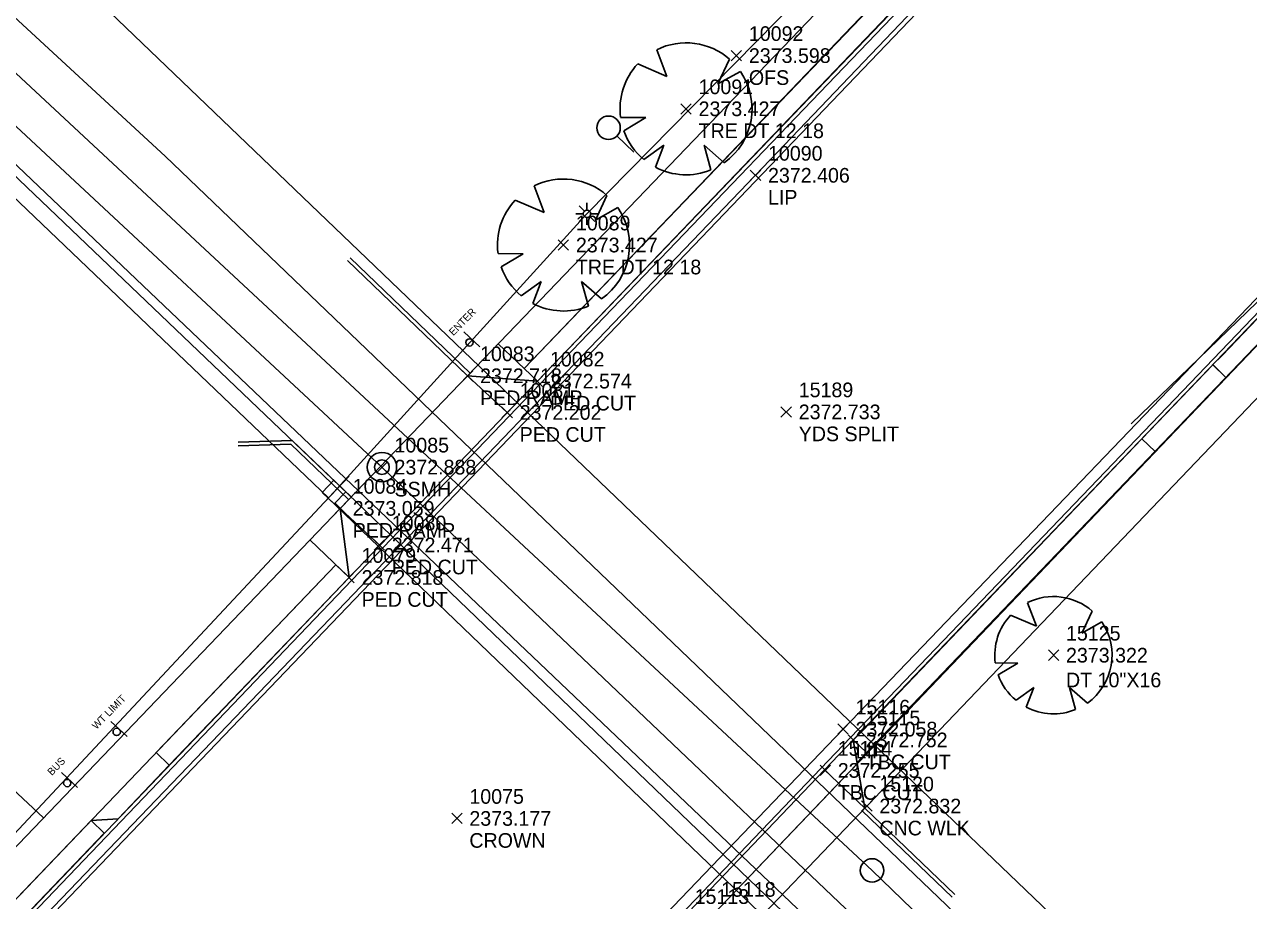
# Model space of a CAD drawing. Extents: x 2377639 to 2379738, y 729875 to 732734.
# Drawn here: x 2378181.6 to 2378348.5, y 730426.6 to 730546.1 of the extents above; entities that cross this region are included whole.
import ezdxf

# ---------------------------------------------------------------- set-up
doc = ezdxf.new("R2010")
doc.units = 0
for name, color, linetype in [('Default', 7, 'Continuous'), ('DES_ROADWAY_Sidewalk', 7, 'Continuous'), ('TOPO_CURBGTR_Back-of-Curb', 7, 'Continuous'), ('TOPO_CURBGTR_Face-of-Curb', 7, 'Continuous'), ('TOPO_CURBGTR_Lip-of-Gutter', 7, 'Continuous'), ('TOPO_DATA_Elevations', 7, 'Continuous'), ('TOPO_DATA_Notes', 7, 'Continuous'), ('TOPO_ELEC_Cable_Overhead-Exist', 7, 'Continuous'), ('TOPO_ELEC_Power-Pole', 7, 'Continuous'), ('TOPO_GAS_Line', 7, 'Continuous'), ('TOPO_LIGHTING_Luminaire-Pole', 7, 'Continuous'), ('TOPO_LNDSCP_Misc', 7, 'Continuous'), ('TOPO_LNDSCP_Tree', 7, 'Continuous'), ('TOPO_MISC_Flat-Asphalt', 7, 'Continuous'), ('TOPO_SAN_Plastic-Pipe', 7, 'Continuous'), ('TOPO_SAN_Sewer-Manhole', 7, 'Continuous'), ('TOPO_SIGNS_Post-Single', 7, 'Continuous'), ('TOPO_STORM_Line-Other', 7, 'Continuous'), ('TOPO_SW_Back', 7, 'Continuous'), ('TOPO_SW_Edge', 7, 'Continuous'), ('TOPO_TELE_Overhead-Line', 7, 'Continuous'), ('TOPO_TV_Cable-Overhead', 7, 'Continuous'), ('TOPO_WTRUTIL_Irrig-Sprinkler', 7, 'Continuous'), ('TOPO_WTRUTIL_Line', 7, 'Continuous'), ('TOPO_WTRUTIL_Spigot', 7, 'Continuous'), ('TOPO_WTRUTIL_Valve', 7, 'Continuous')]:
    doc.layers.add(name, color=color, linetype=linetype)

# ---------------------------------------------------------------- blocks, each defined once
blk = doc.blocks.new('MH_18')
at = {"layer": 'Default'}
for radius in [0.0254, 0.0127]:
    blk.add_circle((0, 0), radius, dxfattribs=at)
blk = doc.blocks.new('DT_1')
at = {"layer": 'Default'}
for p, q in [((-0.037, 0.0625), (-0.0565, 0.1137)), ((0.0838, 0.0954), (0.0615, 0.0479)), ((-0.093, 0.0865), (-0.037, 0.0625)), ((0.0615, 0.0479), (0.1046, 0.072)), ((-0.0773, -0.017), (-0.1259, -0.0164)), ((-0.1198, -0.0422), (-0.0773, -0.017)), ((-0.0426, -0.0702), (-0.0811, -0.0977)), ((-0.059, -0.1125), (-0.0426, -0.0702)), ((0.0734, -0.1037), (0.0346, -0.0702)), ((0.0346, -0.0702), (0.048, -0.1176))]:
    blk.add_line(p, q, dxfattribs=at)
for start, end in [(48.7013, 116.3979), (137.0682, 187.4038), (305.2865, 34.5379), (199.3985, 230.3084), (242.3287, 292.2114)]:
    blk.add_arc((0, 0), 0.127, start, end, dxfattribs=at)
blk = doc.blocks.new('SIGN_6')
at = {"layer": 'Default'}
blk.add_line((0.0064, 0.0197), (0.0064, -0.0185), dxfattribs=at)
blk.add_circle((0, 0), 0.00635, dxfattribs=at)
blk = doc.blocks.new('UP_1')
at = {"layer": 'Default'}
for p, q in [((0, 0.0381), (0, -0.0381)), ((-0.0145, 0.0145), (0.0145, 0.0145)), ((-0.0145, -0.0145), (-0.0145, 0.0145)), ((0.0145, 0.0145), (0.0145, -0.0145)), ((0.0145, -0.0145), (-0.0145, -0.0145))]:
    blk.add_line(p, q, dxfattribs=at)
blk = doc.blocks.new('LITE_2')
at = {"layer": 'Default'}
for p, q in [((-0.0064, 0), (-0.0191, 0)), ((-0.0045, 0.0045), (-0.0135, 0.0135)), ((0, 0.0191), (0, 0.0064)), ((0.0045, 0.0045), (0.0135, 0.0135)), ((0.0191, 0), (0.0064, 0)), ((-0.0135, -0.0135), (-0.0045, -0.0045)), ((0, -0.0064), (0, -0.0191)), ((0.0135, -0.0135), (0.0045, -0.0045))]:
    blk.add_line(p, q, dxfattribs=at)
blk.add_circle((0, 0), 0.00635, dxfattribs=at)

msp = doc.modelspace()

# ---------------------------------------------------------------- linework, layer by layer
at = {"layer": 'DES_ROADWAY_Sidewalk'}
for p, q in [((2378201.32, 730445.03), (2378199.52, 730446.76)), ((2378194.34, 730437.74), (2378201.32, 730445.03)), ((2378184.17, 730437.87), (2378178.51, 730443.14)), ((2378190.66, 730437.5), (2378194.34, 730437.74))]:
    msp.add_line(p, q, dxfattribs=at)
at = {"layer": 'TOPO_CURBGTR_Back-of-Curb'}
for p, q in [((2378242.34, 730498.52), (2378225.97, 730514.27)), ((2378210.71, 730488.6), (2378217.9, 730488.82)), ((2378225.77, 730481.27), (2378217.9, 730488.82)), ((2378296.16, 730439.17), (2378308.44, 730427.4))]:
    msp.add_line(p, q, dxfattribs=at)
for points in [[(2378139.75, 730380.87), (2378148.64, 730390), (2378225.84, 730470.65), (2378251.52, 730497.43), (2378309.29, 730557.66), (2378317.46, 730566.28)], [(2378186.07, 730334.91), (2378191.86, 730341.37), (2378266.29, 730418.91), (2378294.6, 730448.49), (2378365.13, 730522.12)]]:
    msp.add_lwpolyline(points, dxfattribs=at)
at = {"layer": 'TOPO_CURBGTR_Face-of-Curb'}
for p, q in [((2378242, 730498.15), (2378225.62, 730513.91)), ((2378210.7, 730489.1), (2378218.09, 730489.32)), ((2378226.11, 730481.63), (2378218.09, 730489.32)), ((2378295.82, 730438.81), (2378308.09, 730427.04))]:
    msp.add_line(p, q, dxfattribs=at)
for points in [[(2378140.26, 730380.67), (2378149, 730389.65), (2378226.2, 730470.3), (2378251.88, 730497.08), (2378309.66, 730557.31), (2378317.82, 730565.94)], [(2378185.7, 730335.25), (2378191.49, 730341.71), (2378265.93, 730419.26), (2378294.23, 730448.83), (2378364.76, 730522.46)]]:
    msp.add_lwpolyline(points, dxfattribs=at)
at = {"layer": 'TOPO_CURBGTR_Lip-of-Gutter'}
for points in [[(2378319.9, 730566.2), (2378310.75, 730556.45), (2378281.26, 730525.51), (2378150.03, 730388.75), (2378141.73, 730380.11)], [(2378184.52, 730336.46), (2378190.48, 730342.62), (2378264.81, 730420.32), (2378293.2, 730449.96), (2378361.38, 730521)]]:
    msp.add_lwpolyline(points, dxfattribs=at)
at = {"layer": 'TOPO_DATA_Elevations'}
for p, q in [((2378277.95, 730541.14), (2378279.36, 730542.55)), ((2378277.95, 730542.55), (2378279.36, 730541.14)), ((2378271.09, 730533.87), (2378272.5, 730535.28)), ((2378271.09, 730535.28), (2378272.5, 730533.87)), ((2378280.55, 730524.81), (2378281.97, 730526.22)), ((2378280.55, 730526.22), (2378281.97, 730524.81)), ((2378254.36, 730515.29), (2378255.77, 730516.7)), ((2378254.36, 730516.7), (2378255.77, 730515.29)), ((2378241.29, 730497.45), (2378242.7, 730498.86)), ((2378241.29, 730498.86), (2378242.7, 730497.45)), ((2378250.81, 730496.72), (2378252.23, 730498.13)), ((2378250.81, 730498.13), (2378252.23, 730496.72)), ((2378246.69, 730492.45), (2378248.1, 730493.87)), ((2378246.69, 730493.87), (2378248.1, 730492.45)), ((2378284.74, 730492.54), (2378286.16, 730493.95)), ((2378284.74, 730493.95), (2378286.16, 730492.54)), ((2378229.61, 730484.99), (2378231.03, 730486.4)), ((2378229.61, 730486.4), (2378231.03, 730484.99)), ((2378223.92, 730479.38), (2378225.33, 730480.79)), ((2378223.92, 730480.79), (2378225.33, 730479.38)), ((2378229.25, 730474.37), (2378230.66, 730475.79)), ((2378229.25, 730475.79), (2378230.66, 730474.37)), ((2378225.13, 730469.94), (2378226.54, 730471.36)), ((2378225.13, 730471.36), (2378226.54, 730469.94)), ((2378321.2, 730459.34), (2378322.61, 730460.76)), ((2378321.2, 730460.76), (2378322.61, 730459.34)), ((2378292.5, 730449.26), (2378293.91, 730450.67)), ((2378292.5, 730450.67), (2378293.91, 730449.26)), ((2378293.89, 730447.78), (2378295.3, 730449.19)), ((2378293.89, 730449.19), (2378295.3, 730447.78)), ((2378290.06, 730443.62), (2378291.48, 730445.04)), ((2378290.06, 730445.04), (2378291.48, 730443.62)), ((2378295.74, 730438.76), (2378297.16, 730440.18)), ((2378295.74, 730440.18), (2378297.16, 730438.76)), ((2378239.83, 730437.08), (2378241.24, 730438.49)), ((2378239.83, 730438.49), (2378241.24, 730437.08))]:
    msp.add_line(p, q, dxfattribs=at)
at = {"layer": 'TOPO_ELEC_Cable_Overhead-Exist'}
for p, q in [((2378223.04, 730481.51), (2378021.37, 730674.12)), ((2378179.49, 730434.93), (2378223.77, 730482.29)), ((2378388.98, 730322.09), (2378222.92, 730481.5))]:
    msp.add_line(p, q, dxfattribs=at)
msp.add_lwpolyline([(2378223.77, 730482.29), (2378258.28, 730520.27), (2378318.81, 730581.84)], dxfattribs=at)
at = {"layer": 'TOPO_GAS_Line'}
for p, q in [((2378200.77, 730528.13), (2378072.42, 730646.31)), ((2378589.02, 730155.86), (2378200.77, 730528.13))]:
    msp.add_line(p, q, dxfattribs=at)
at = {"layer": 'TOPO_LNDSCP_Misc'}
for points in [[(2378343.64, 730499.68), (2378344.89, 730500.91), (2378365.13, 730522.12), (2378366.93, 730520.39), (2378345.43, 730497.94)], [(2378294.6, 730448.49), (2378295.86, 730449.73), (2378333.95, 730489.56), (2378335.75, 730487.83), (2378296.4, 730446.76)]]:
    msp.add_lwpolyline(points, close=True, dxfattribs=at)
at = {"layer": 'TOPO_MISC_Flat-Asphalt'}
for points in [[(2378249.71, 730499.16), (2378316.29, 730568.7), (2378318.09, 730566.97), (2378251.52, 730497.43)], [(2378199.52, 730446.76), (2378224.04, 730472.37), (2378225.84, 730470.65), (2378201.32, 730445.04)], [(2378142.93, 730387.65), (2378190.64, 730437.48), (2378192.44, 730435.75), (2378144.73, 730385.92)]]:
    msp.add_lwpolyline(points, close=True, dxfattribs=at)
at = {"layer": 'TOPO_SAN_Plastic-Pipe'}
for p, q in [((2378230.32, 730485.7), (2378026.56, 730675.45)), ((2378505.67, 730223.51), (2378230.32, 730485.7))]:
    msp.add_line(p, q, dxfattribs=at)
at = {"layer": 'TOPO_STORM_Line-Other'}
for p, q in [((2378608.31, 730773.03), (2378187, 730332.08)), ((2378608.31, 730773.03), (2378188.38, 730333.53)), ((2378361.37, 730519.55), (2378332.49, 730491.61))]:
    msp.add_line(p, q, dxfattribs=at)
at = {"layer": 'TOPO_SW_Back'}
for p, q in [((2378251.52, 730497.43), (2378246.19, 730502.53)), ((2378242, 730498.15), (2378247.41, 730493.15)), ((2378224.62, 730480.08), (2378230.02, 730475.01)), ((2378225.84, 730470.65), (2378220.49, 730475.77))]:
    msp.add_line(p, q, dxfattribs=at)
for points in [[(2378242, 730498.15), (2378303.75, 730562.56), (2378314.97, 730574.3), (2378310.86, 730589.97), (2378304.71, 730595.69)], [(2378249.71, 730499.16), (2378249.71, 730499.16), (2378306.54, 730558.42), (2378316.31, 730568.66), (2378318.09, 730566.97)], [(2378295.11, 730445.41), (2378296.4, 730446.76), (2378366.93, 730520.39), (2378365.13, 730522.12)], [(2378397.25, 730507), (2378388.6, 730515.23), (2378372.58, 730519.09), (2378370.25, 730516.61), (2378296.45, 730439.47), (2378277.39, 730419.55), (2378268.61, 730410.41)], [(2378225.84, 730470.65), (2378224.62, 730480.08), (2378242, 730498.15), (2378251.52, 730497.43)], [(2378133.7, 730396.49), (2378139.26, 730391), (2378146.3, 730398.35), (2378224.62, 730480.08)], [(2378224.03, 730472.38), (2378146.72, 730391.58), (2378142.93, 730387.65), (2378144.69, 730385.94)], [(2378290.69, 730444.41), (2378296.16, 730439.17), (2378294.6, 730448.49)]]:
    msp.add_lwpolyline(points, dxfattribs=at)
at = {"layer": 'TOPO_SW_Edge'}
for p, q in [((2378333.95, 730489.56), (2378343.63, 730499.67)), ((2378343.63, 730499.67), (2378345.43, 730497.94)), ((2378333.95, 730489.56), (2378335.75, 730487.83))]:
    msp.add_line(p, q, dxfattribs=at)
at = {"layer": 'TOPO_TELE_Overhead-Line'}
for p, q in [((2378224.56, 730483.12), (2378116.66, 730586.12)), ((2378390.57, 730323.64), (2378224.56, 730483.12))]:
    msp.add_line(p, q, dxfattribs=at)
at = {"layer": 'TOPO_TV_Cable-Overhead'}
msp.add_line((2378432.32, 730287.11), (2378021.81, 730677.94), dxfattribs=at)
at = {"layer": 'TOPO_WTRUTIL_Irrig-Sprinkler'}
msp.add_line((2378389.7, 730359.39), (2378171.36, 730568.74), dxfattribs=at)
at = {"layer": 'TOPO_WTRUTIL_Line'}
for p, q in [((2378027.31, 730681.99), (2378297.16, 730430.69)), ((2378133.36, 730370.41), (2378391.81, 730640.09)), ((2378518.53, 730217.39), (2378297.16, 730430.69))]:
    msp.add_line(p, q, dxfattribs=at)
at = {"layer": 'TOPO_WTRUTIL_Spigot'}
msp.add_line((2378264.68, 730528.66), (2378262.37, 730530.88), dxfattribs=at)
msp.add_circle((2378261.22, 730531.99), 1.6, dxfattribs=at)
at = {"layer": 'TOPO_WTRUTIL_Valve'}
msp.add_circle((2378297.16, 730430.69), 1.6, dxfattribs=at)

# ---------------------------------------------------------------- block references
at = {"layer": 'TOPO_ELEC_Power-Pole', "xscale": 78.74000000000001, "yscale": 78.74, "rotation": -43.76602493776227}
msp.add_blockref('UP_1', (2378223.77, 730482.29), dxfattribs=at)
at = {"layer": 'TOPO_LIGHTING_Luminaire-Pole', "xscale": 78.74000000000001, "yscale": 78.74000000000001}
msp.add_blockref('LITE_2', (2378258.28, 730520.27), dxfattribs=at)
at = {"layer": 'TOPO_LNDSCP_Tree'}
for p, xscale, yscale in [((2378271.79, 730534.58), 70.866, 70.866), ((2378255.07, 730516), 70.866, 70.866), ((2378321.9, 730460.05), 62.992000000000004, 62.992000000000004)]:
    msp.add_blockref('DT_1', p, dxfattribs=dict(at, xscale=xscale, yscale=yscale))
at = {"layer": 'TOPO_SAN_Sewer-Manhole', "xscale": 78.74000000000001, "yscale": 78.74000000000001}
msp.add_blockref('MH_18', (2378230.32, 730485.7), dxfattribs=at)
at = {"layer": 'TOPO_SIGNS_Post-Single', "xscale": 78.74000000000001, "yscale": 78.74, "rotation": 47.14071663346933}
for p in [(2378242.27, 730502.72), (2378194.14, 730449.58), (2378187.4, 730442.61)]:
    msp.add_blockref('SIGN_6', p, dxfattribs=at)

# ---------------------------------------------------------------- texts
at = {"layer": 'TOPO_DATA_Elevations'}
for s, p in [('10092', (2378280.36, 730543.84)), ('2373.598', (2378280.36, 730540.84)), ('OFS', (2378280.36, 730537.84)), ('10091', (2378273.5, 730536.58)), ('2373.427', (2378273.5, 730533.58)), ('TRE DT 12 18', (2378273.5, 730530.58)), ('10090', (2378282.97, 730527.51)), ('2372.406', (2378282.97, 730524.51)), ('LIP', (2378282.97, 730521.51)), ('10089', (2378256.77, 730518)), ('2373.427', (2378256.77, 730515)), ('TRE DT 12 18', (2378256.77, 730512)), ('10083', (2378243.7, 730500.16)), ('10082', (2378253.23, 730499.43)), ('2372.718', (2378243.7, 730497.16)), ('2372.574', (2378253.23, 730496.43)), ('PED RAMP', (2378243.7, 730494.16)), ('10081', (2378249.1, 730495.16)), ('15189', (2378287.16, 730495.24)), ('2372.202', (2378249.1, 730492.16)), ('PED CUT', (2378253.23, 730493.43)), ('2372.733', (2378287.16, 730492.24)), ('PED CUT', (2378249.1, 730489.16)), ('YDS SPLIT', (2378287.16, 730489.24)), ('10085', (2378232.03, 730487.7)), ('2372.888', (2378232.03, 730484.7)), ('10084', (2378226.33, 730482.08)), ('SSMH', (2378232.03, 730481.7)), ('2373.059', (2378226.33, 730479.08)), ('10080', (2378231.66, 730477.08)), ('PED RAMP', (2378226.33, 730476.08)), ('2372.471', (2378231.66, 730474.08)), ('10079', (2378227.54, 730472.65)), ('PED CUT', (2378231.66, 730471.08)), ('2372.818', (2378227.54, 730469.65)), ('PED CUT', (2378227.54, 730466.65)), ('15125', (2378323.61, 730462.05)), ('2373.322', (2378323.61, 730459.05)), ('DT 10"X16', (2378323.61, 730455.67)), ('15116', (2378294.91, 730451.96)), ('15115', (2378296.3, 730450.49)), ('2372.058', (2378294.91, 730448.96)), ('2372.752', (2378296.3, 730447.49)), ('15114', (2378292.48, 730446.33)), ('LIP', (2378294.91, 730445.96)), ('TBC CUT', (2378296.3, 730444.49)), ('2372.255', (2378292.48, 730443.33)), ('TBC CUT', (2378292.48, 730440.33)), ('15120', (2378298.16, 730441.47)), ('10075', (2378242.24, 730439.78)), ('2372.832', (2378298.16, 730438.47)), ('2373.177', (2378242.24, 730436.78)), ('CNC WLK', (2378298.16, 730435.47)), ('CROWN', (2378242.24, 730433.78)), ('15118', (2378276.57, 730427.1)), ('15113', (2378272.96, 730426.12))]:
    msp.add_text(s, height=2, dxfattribs=at).set_placement(p)
at = {"layer": 'TOPO_DATA_Notes'}
for s, p in [('ENTER', (2378240.06, 730503.56)), ('WT LIMIT', (2378191.38, 730449.85)), ('BUS', (2378185.3, 730443.56))]:
    msp.add_text(s, height=1, rotation=45.6392, dxfattribs=at).set_placement(p)

doc.saveas('drawing.dxf')
